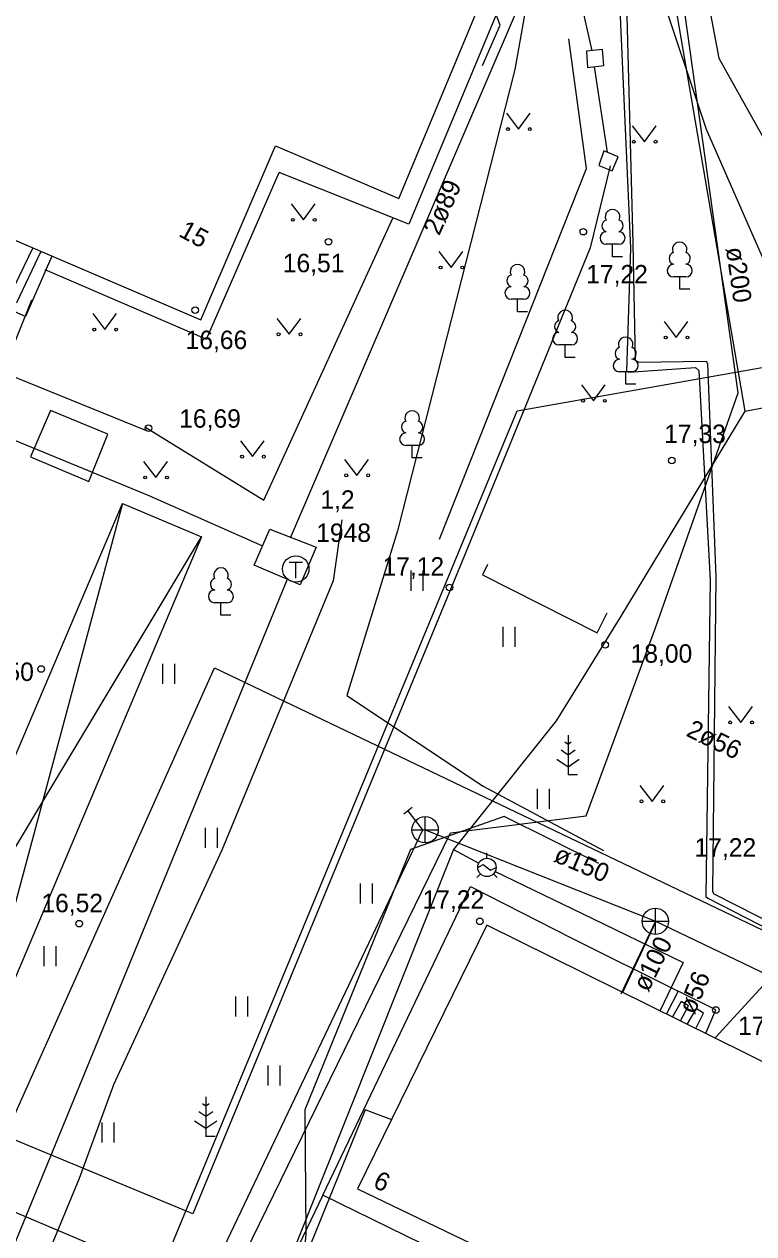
# Model space of a CAD drawing. Extents: x 713540 to 713867, y 6589774 to 6590061.
# Drawn here: x 713614.29 to 713641.99, y 6589963.85 to 6590009.83 of the extents above; entities that cross this region are included whole.
import ezdxf

# ---------------------------------------------------------------- set-up
doc = ezdxf.new("R2010")
doc.units = 0
for name, color, linetype in [('AED', 7, 'Continuous'), ('HALJASTUS', 7, 'Continuous'), ('HOONE', 7, 'Continuous'), ('HOONEDET', 7, 'Continuous'), ('KAEVU_NR', 7, 'Continuous'), ('KKAEV', 7, 'Continuous'), ('KORGUS', 7, 'Continuous'), ('KTRASS', 7, 'Continuous'), ('MPKAABEL', 7, 'Continuous'), ('PUU', 7, 'Continuous'), ('SITRASS', 7, 'Continuous'), ('TEE', 7, 'Continuous'), ('TKAEV', 7, 'Continuous'), ('TORU NR', 7, 'Continuous'), ('TTRASS', 7, 'Continuous'), ('VTRASS', 7, 'Continuous'), ('Слой 1', 7, 'Continuous')]:
    doc.layers.add(name, color=color, linetype=linetype)

msp = doc.modelspace()

# ---------------------------------------------------------------- linework, layer by layer
at = {"layer": 'AED'}
for points in [[(713618.488, 6590037.946), (713619.001, 6590034.99), (713622.312, 6590035.031), (713628.353, 6590032.257), (713630.993, 6590030.365), (713635.85, 6590008.82)], [(713635.64, 6590008.8), (713635.68, 6590008.18), (713636.3, 6590008.26), (713636.25, 6590008.86), (713635.64, 6590008.8)], [(713635.93, 6590008.21), (713636.42, 6590004.96)], [(713636.3, 6590005.01), (713636.11, 6590004.46), (713636.62, 6590004.25), (713636.85, 6590004.79), (713636.3, 6590005.01)], [(713636.535, 6590004.444), (713635.778, 6590001.331), (713631.008, 6589989.639), (713620.691, 6589964.611), (713584.43, 6589979.666), (713562.034, 6589989.021), (713563.098, 6589991.568)], [(713631.88, 6589989.288), (713631.697, 6589988.893), (713636.045, 6589986.694), (713636.43, 6589987.455)]]:
    msp.add_lwpolyline(points, dxfattribs=at)
at = {"layer": 'HALJASTUS'}
for p, q in [((713632.597, 6590006.447), (713633.06, 6590005.84)), ((713633.06, 6590005.84), (713633.506, 6590006.447)), ((713637.377, 6590005.967), (713637.84, 6590005.36)), ((713637.84, 6590005.36), (713638.286, 6590005.967)), ((713624.427, 6590002.997), (713624.89, 6590002.39)), ((713624.89, 6590002.39), (713625.336, 6590002.997)), ((713630.037, 6590001.187), (713630.5, 6590000.58)), ((713630.5, 6590000.58), (713630.946, 6590001.187)), ((713616.887, 6589998.827), (713617.35, 6589998.22)), ((713617.35, 6589998.22), (713617.796, 6589998.827)), ((713623.887, 6589998.647), (713624.35, 6589998.04)), ((713624.35, 6589998.04), (713624.796, 6589998.647)), ((713638.587, 6589998.527), (713639.05, 6589997.92)), ((713639.05, 6589997.92), (713639.496, 6589998.527)), ((713635.447, 6589996.117), (713635.91, 6589995.51)), ((713635.91, 6589995.51), (713636.356, 6589996.117)), ((713622.497, 6589993.997), (713622.96, 6589993.39)), ((713622.96, 6589993.39), (713623.406, 6589993.997)), ((713618.817, 6589993.207), (713619.28, 6589992.6)), ((713619.28, 6589992.6), (713619.726, 6589993.207)), ((713626.457, 6589993.287), (713626.92, 6589992.68)), ((713626.92, 6589992.68), (713627.366, 6589993.287)), ((713628.969, 6589989.058), (713628.969, 6589988.297)), ((713629.424, 6589989.058), (713629.424, 6589988.297)), ((713632.461, 6589986.926), (713632.461, 6589986.165)), ((713632.916, 6589986.926), (713632.916, 6589986.165)), ((713619.54, 6589985.522), (713619.54, 6589984.761)), ((713619.996, 6589985.522), (713619.996, 6589984.761)), ((713641.037, 6589983.897), (713641.5, 6589983.29)), ((713641.5, 6589983.29), (713641.946, 6589983.897)), ((713637.667, 6589980.897), (713638.13, 6589980.29)), ((713638.13, 6589980.29), (713638.576, 6589980.897)), ((713633.772, 6589980.771), (713633.772, 6589980.009)), ((713634.228, 6589980.771), (713634.228, 6589980.009)), ((713621.158, 6589979.286), (713621.158, 6589978.525)), ((713621.613, 6589979.286), (713621.613, 6589978.525)), ((713627.048, 6589977.166), (713627.048, 6589976.405)), ((713627.503, 6589977.166), (713627.503, 6589976.405)), ((713615.034, 6589974.782), (713615.034, 6589974.021)), ((713615.489, 6589974.782), (713615.489, 6589974.021)), ((713622.314, 6589972.876), (713622.314, 6589972.115)), ((713622.769, 6589972.876), (713622.769, 6589972.115)), ((713623.539, 6589970.251), (713623.539, 6589969.49)), ((713623.994, 6589970.251), (713623.994, 6589969.49)), ((713617.23, 6589968.083), (713617.23, 6589967.322)), ((713617.685, 6589968.083), (713617.685, 6589967.322))]:
    msp.add_line(p, q, dxfattribs=at)
for points in [[(713630.058, 6589990.26), (713635.64, 6590004.34), (713634.972, 6590009.265)], [(713618.87, 6589994.52), (713623.39, 6589991.74), (713628.29, 6590002.46)], [(713618.911, 6589994.383), (713603.441, 6590000.663)]]:
    msp.add_lwpolyline(points, dxfattribs=at)
for centre in [(713632.659, 6590005.84), (713633.488, 6590005.84), (713637.439, 6590005.36), (713638.268, 6590005.36), (713624.489, 6590002.39), (713625.318, 6590002.39), (713630.099, 6590000.58), (713630.928, 6590000.58), (713616.949, 6589998.22), (713617.778, 6589998.22), (713623.949, 6589998.04), (713624.778, 6589998.04), (713638.649, 6589997.92), (713639.478, 6589997.92), (713635.509, 6589995.51), (713636.338, 6589995.51), (713622.559, 6589993.39), (713623.388, 6589993.39), (713626.519, 6589992.68), (713627.348, 6589992.68), (713618.879, 6589992.6), (713619.708, 6589992.6), (713641.099, 6589983.29), (713641.928, 6589983.29), (713637.729, 6589980.29), (713638.558, 6589980.29)]:
    msp.add_circle(centre, 0.055, dxfattribs=at)
at = {"layer": 'HOONE'}
for p, q in [((713631.86, 6589978.13), (713631.86, 6589978.327)), ((713631.51, 6589977.778), (713631.721, 6589977.884)), ((713631.721, 6589977.884), (713631.999, 6589977.676)), ((713631.999, 6589977.676), (713632.21, 6589977.782)), ((713631.613, 6589977.533), (713631.473, 6589977.393)), ((713632.107, 6589977.533), (713632.247, 6589977.393))]:
    msp.add_line(p, q, dxfattribs=at)
for points in [[(713630.482, 6590060.636), (713633.183, 6590044.481), (713637.86, 6590017.28), (713638.858, 6590011.457), (713641.66, 6589995.12)], [(713611.945, 6590002.466), (713620.997, 6589998.591), (713623.828, 6590005.205), (713628.509, 6590003.201), (713631.396, 6590010.137), (713626.176, 6590012.308), (713625.646, 6590010.977), (713612.515, 6590016.682)], [(713641.66, 6589995.12), (713651.08, 6589996.88), (713659.244, 6589998.419), (713687.328, 6590003.385)], [(713641.66, 6589995.12), (713636.91, 6589987.262), (713634.49, 6589983.35), (713630.59, 6589978.46), (713620.519, 6589953.184), (713616.638, 6589944.685)], [(713665.097, 6589994.469), (713654.36, 6589992.62), (713659, 6589966.87), (713655.32, 6589963.97), (713631.86, 6589975.579), (713626.949, 6589965.568), (713655.111, 6589952.011), (713657.717, 6589953.998), (713658.827, 6589952.543), (713664.692, 6589957.048), (713664.664, 6589957.055), (713669.225, 6589960.582), (713668.167, 6589961.969), (713670.71, 6589963.909), (713665.097, 6589994.469)], [(713621.015, 6589990.338), (713611.877, 6589968.717), (713608.872, 6589970.068), (713618.021, 6589991.61), (713621.015, 6589990.338)], [(713630.59, 6589978.46), (713631.548, 6589977.939)], [(713632.171, 6589977.62), (713635.446, 6589976.042), (713639.31, 6589974.17), (713638.44, 6589972.34)]]:
    msp.add_lwpolyline(points, dxfattribs=at)
msp.add_circle((713631.86, 6589977.78), 0.35, dxfattribs=at)
at = {"layer": 'HOONEDET'}
for p, q in [((713618.021, 6589991.61), (713611.877, 6589968.717)), ((713608.872, 6589970.068), (713621.015, 6589990.338))]:
    msp.add_line(p, q, dxfattribs=at)
for points in [[(713625.431, 6590012.462), (713625.762, 6590013.293), (713632.366, 6590010.546), (713628.89, 6590002.231), (713623.97, 6590004.19)], [(713621.21, 6589997.86), (713623.97, 6590004.19)], [(713615.337, 6590001.014), (713614.341, 6589998.723), (713611.671, 6589999.883), (713612.664, 6590002.158)], [(713614.921, 6590001.192), (713613.991, 6589999.233), (713612.321, 6590000.023), (713613.163, 6590001.945)], [(713614.614, 6590001.323), (713613.921, 6589999.883), (713612.921, 6590000.283), (713613.559, 6590001.775)], [(713615.07, 6590000.5), (713621.21, 6589997.86)], [(713654.365, 6589993.337), (713665.759, 6589995.354), (713671.737, 6589963.499), (713669.522, 6589961.81), (713670.612, 6589960.382), (713665.868, 6589956.768), (713665.7, 6589956.808), (713658.611, 6589951.238), (713657.507, 6589952.685), (713655.117, 6589950.862), (713625.629, 6589965.327), (713631.231, 6589977.05), (713635.106, 6589975.077), (713639.12, 6589973.07)], [(713640.17, 6589971.48), (713640.55, 6589972.36), (713639.12, 6589973.07), (713638.68, 6589972.22)], [(713639.21, 6589971.95), (713639.51, 6589972.52), (713639.24, 6589972.68), (713638.91, 6589972.1)], [(713639.79, 6589971.66), (713640.09, 6589972.24), (713639.81, 6589972.42), (713639.47, 6589971.83)]]:
    msp.add_lwpolyline(points, dxfattribs=at)
at = {"layer": 'KKAEV'}
for p, q in [((713629.514, 6589978.71), (713629.514, 6589979.71)), ((713629.014, 6589979.21), (713630.014, 6589979.21)), ((713638.256, 6589975.233), (713638.256, 6589976.233)), ((713637.756, 6589975.733), (713638.756, 6589975.733))]:
    msp.add_line(p, q, dxfattribs=at)
for centre in [(713629.514, 6589979.21), (713638.256, 6589975.733)]:
    msp.add_circle(centre, 0.5, dxfattribs=at)
at = {"layer": 'KORGUS'}
for centre in [(713635.52, 6590001.94), (713625.84, 6590001.56), (713620.78, 6589998.96), (713619.01, 6589994.47), (713638.88, 6589993.24), (713630.44, 6589988.42), (713636.35, 6589986.24), (713614.93, 6589985.32), (713616.37, 6589975.64), (713631.59, 6589975.73), (713640.55, 6589972.36)]:
    msp.add_circle(centre, 0.125, dxfattribs=at)
at = {"layer": 'KTRASS'}
for p, q in [((713628.709, 6589979.819), (713629.018, 6589980.071)), ((713629.42, 6589979.213), (713628.859, 6589979.941)), ((713620.824, 6589961.132), (713629.42, 6589979.213))]:
    msp.add_line(p, q, dxfattribs=at)
for points in [[(713629.514, 6589979.21), (713638.256, 6589975.733)], [(713638.256, 6589975.733), (713636.946, 6589972.966)], [(713637.02, 6589973.04), (713638.29, 6589975.73)], [(713638.256, 6589975.733), (713644.655, 6589972.669)]]:
    msp.add_lwpolyline(points, dxfattribs=at)
at = {"layer": 'MPKAABEL'}
for points in [[(713634.872, 6590060.636), (713637.296, 6590044.981), (713639.214, 6590034.99), (713641.55, 6590020.81), (713640.247, 6590018.756), (713639.99, 6590012.096), (713640.67, 6590008.54), (713653.54, 6589985.5)], [(713631.696, 6590008.26), (713632.361, 6590009.786), (713631.878, 6590011.07), (713626.458, 6590013.001), (713624.501, 6590013.754), (713622.661, 6590013.508), (713613.306, 6590017.006)], [(713613.314, 6590017.025), (713622.509, 6590013.848), (713624.668, 6590014.258), (713633.443, 6590011.043), (713632.914, 6590008.103), (713628.469, 6589990.573), (713626.542, 6589984.315), (713631.711, 6589980.868), (713636.285, 6589978.421)], [(713626.354, 6589990.991), (713626.025, 6589988.675), (713621.796, 6589978.429), (713617.679, 6589969.517), (713616.38, 6589965.95), (713614.069, 6589960.385), (713612.538, 6589956.831), (713611.255, 6589953.855), (713609.284, 6589948.917), (713608.569, 6589945.656), (713614.381, 6589942.657), (713608.627, 6589929.201), (713606.65, 6589925.56), (713594.15, 6589930.93)], [(713640.53, 6589971.3), (713653.54, 6589985.5)], [(713636.109, 6589977.923), (713632.516, 6589979.71), (713628.954, 6589978.46), (713624.941, 6589968.562), (713624.988, 6589963.846), (713624.228, 6589955.304), (713624.309, 6589951.452), (713624.444, 6589944.99), (713624.264, 6589942.119), (713627.907, 6589940.465), (713624.829, 6589930.433), (713621.405, 6589921.156), (713617.009, 6589909.766)]]:
    msp.add_lwpolyline(points, dxfattribs=at)
at = {"layer": 'PUU'}
for p, q in [((713636.87, 6590001.465), (713636.39, 6590001.465)), ((713636.63, 6590000.99), (713636.63, 6590001.465)), ((713637.01, 6590000.99), (713636.63, 6590000.99)), ((713639.42, 6590000.225), (713638.94, 6590000.225)), ((713639.18, 6589999.75), (713639.18, 6590000.225)), ((713639.56, 6589999.75), (713639.18, 6589999.75)), ((713633.26, 6589999.375), (713632.78, 6589999.375)), ((713633.02, 6589998.9), (713633.02, 6589999.375)), ((713633.4, 6589998.9), (713633.02, 6589998.9)), ((713635.07, 6589997.635), (713634.59, 6589997.635)), ((713634.83, 6589997.16), (713634.83, 6589997.635)), ((713635.21, 6589997.16), (713634.83, 6589997.16)), ((713637.37, 6589996.615), (713636.89, 6589996.615)), ((713637.13, 6589996.14), (713637.13, 6589996.615)), ((713637.51, 6589996.14), (713637.13, 6589996.14)), ((713629.26, 6589993.815), (713628.78, 6589993.815)), ((713629.02, 6589993.34), (713629.02, 6589993.815)), ((713629.4, 6589993.34), (713629.02, 6589993.34)), ((713621.999, 6589987.841), (713621.519, 6589987.841)), ((713621.759, 6589987.366), (713621.759, 6589987.841)), ((713622.139, 6589987.366), (713621.759, 6589987.366)), ((713634.941, 6589982.801), (713634.941, 6589981.301)), ((713634.941, 6589982.051), (713634.674, 6589982.229)), ((713634.941, 6589982.451), (713634.817, 6589982.534)), ((713635.065, 6589982.534), (713634.941, 6589982.451)), ((713635.208, 6589982.229), (713634.941, 6589982.051)), ((713634.517, 6589981.891), (713634.941, 6589981.608)), ((713634.941, 6589981.608), (713635.365, 6589981.891)), ((713635.301, 6589981.301), (713634.941, 6589981.301)), ((713621.181, 6589969.056), (713621.181, 6589967.556)), ((713621.181, 6589968.306), (713620.915, 6589968.484)), ((713621.181, 6589968.706), (713621.057, 6589968.789)), ((713621.306, 6589968.789), (713621.181, 6589968.706)), ((713621.448, 6589968.484), (713621.181, 6589968.306)), ((713620.757, 6589968.145), (713621.181, 6589967.863)), ((713621.181, 6589967.863), (713621.605, 6589968.145)), ((713621.541, 6589967.556), (713621.181, 6589967.556))]:
    msp.add_line(p, q, dxfattribs=at)
for centre, radius, start, end in [((713636.46, 6590002.163), 0.233, 109.0217, 253.1415), ((713636.63, 6590002.51), 0.277, 332.5799, 207.4201), ((713636.8, 6590002.163), 0.233, 286.8508, 70.9859), ((713636.393, 6590001.702), 0.238, 90.0016, 269.3953), ((713636.867, 6590001.702), 0.238, 270.6047, 89.9984), ((713639.18, 6590001.27), 0.277, 332.5799, 207.4201), ((713639.01, 6590000.923), 0.233, 109.0217, 253.1415), ((713639.35, 6590000.923), 0.233, 286.8508, 70.9859), ((713633.02, 6590000.42), 0.277, 332.5799, 207.4201), ((713638.943, 6590000.462), 0.238, 90.0016, 269.3953), ((713639.417, 6590000.462), 0.238, 270.6047, 89.9984), ((713632.85, 6590000.073), 0.233, 109.0217, 253.1415), ((713633.19, 6590000.073), 0.233, 286.8508, 70.9859), ((713632.783, 6589999.612), 0.238, 90.0016, 269.3953), ((713633.257, 6589999.612), 0.238, 270.6047, 89.9984), ((713634.83, 6589998.68), 0.277, 332.5799, 207.4201), ((713634.66, 6589998.333), 0.233, 109.0217, 253.1415), ((713635, 6589998.333), 0.233, 286.8508, 70.9859), ((713634.593, 6589997.872), 0.238, 90.0016, 269.3953), ((713635.067, 6589997.872), 0.238, 270.6047, 89.9984), ((713637.13, 6589997.66), 0.277, 332.5799, 207.4201), ((713636.96, 6589997.313), 0.233, 109.0217, 253.1415), ((713637.3, 6589997.313), 0.233, 286.8508, 70.9859), ((713636.893, 6589996.852), 0.238, 90.0016, 269.3953), ((713637.367, 6589996.852), 0.238, 270.6047, 89.9984), ((713629.02, 6589994.86), 0.277, 332.5799, 207.4201), ((713628.85, 6589994.513), 0.233, 109.0217, 253.1415), ((713629.19, 6589994.513), 0.233, 286.8508, 70.9859), ((713628.783, 6589994.052), 0.238, 90.0016, 269.3953), ((713629.257, 6589994.052), 0.238, 270.6047, 89.9984), ((713621.759, 6589988.886), 0.277, 332.5799, 207.4201), ((713621.589, 6589988.539), 0.233, 109.0217, 253.1415), ((713621.929, 6589988.539), 0.233, 286.8508, 70.9859), ((713621.521, 6589988.079), 0.238, 90.0016, 269.3953), ((713621.996, 6589988.079), 0.238, 270.6047, 89.9984)]:
    msp.add_arc(centre, radius, start, end, dxfattribs=at)
at = {"layer": 'SITRASS'}
for points in [[(713634.735, 6590060.636), (713639.6, 6590031.34), (713639.42, 6590021.66), (713636.56, 6590016.77), (713638.404, 6590011.201), (713640.18, 6590005.84), (713646.71, 6589990.97), (713657.77, 6589965.9)], [(713628.246, 6589968.19), (713627.234, 6589968.567), (713624.83, 6589962.636), (713623.526, 6589951.809), (713623.516, 6589951.814), (713622.543, 6589943.796)]]:
    msp.add_lwpolyline(points, dxfattribs=at)
at = {"layer": 'TEE'}
for points in [[(713614.57, 6589999.34), (713613.707, 6589997.19), (713603.922, 6590001.326), (713591.825, 6589974.045), (713621.261, 6589961.576), (713622.688, 6589963.147), (713630.481, 6589979.098), (713635.632, 6589979.743), (713638.264, 6589986.883), (713641.401, 6589995.818), (713639.191, 6590011.645), (713635.853, 6590032.559), (713631.194, 6590060.636)], [(713615.29, 6589995.15), (713614.52, 6589993.38)], [(713617.46, 6589994.25), (713615.29, 6589995.15)], [(713616.74, 6589992.45), (713617.46, 6589994.25)], [(713614.52, 6589993.38), (713616.74, 6589992.45)], [(713625.629, 6589965.327), (713624.266, 6589962.475), (713623.751, 6589960.756), (713641.009, 6589953.207), (713653.169, 6589948.075), (713657.982, 6589947.86), (713664.159, 6589951.614), (713669.174, 6589954.004), (713672.84, 6589955.104)]]:
    msp.add_lwpolyline(points, dxfattribs=at)
at = {"layer": 'TKAEV'}
for p, q in [((713624.351, 6589989.374), (713624.851, 6589989.374)), ((713624.601, 6589988.774), (713624.601, 6589989.374))]:
    msp.add_line(p, q, dxfattribs=at)
msp.add_circle((713624.601, 6589989.124), 0.5, dxfattribs=at)
at = {"layer": 'TTRASS'}
for points in [[(713628.896, 6590060.636), (713628.908, 6590060.564), (713631.035, 6590048.786), (713632.894, 6590037.061), (713635.242, 6590025.21), (713636.781, 6590013.249), (713637.307, 6590001.316), (713637.157, 6589996.645), (713637.245, 6589996.6), (713639.784, 6589996.778), (713639.911, 6589996.659), (713640.338, 6589988.697), (713640.169, 6589976.679), (713640.253, 6589976.609), (713650.804, 6589971.182), (713650.915, 6589970.999), (713652.857, 6589965.719), (713652.647, 6589965.295)], [(713629.199, 6590060.636), (713631.21, 6590049.147), (713633.256, 6590037.367), (713635.386, 6590025.437), (713637.081, 6590013.496), (713637.406, 6590001.507), (713637.495, 6589997.061), (713637.616, 6589996.981), (713640.19, 6589997.018), (713640.241, 6589996.932), (713640.549, 6589988.818), (713640.423, 6589976.86), (713640.479, 6589976.779), (713651.149, 6589971.354), (713651.264, 6589971.081), (713653.226, 6589965.534), (713653.017, 6589965.111)], [(713633.747, 6590012.114), (713624.389, 6589990.298)], [(713609.26, 6589995.35), (713610.09, 6589995.59), (713619.026, 6589991.91), (713623.336, 6589990.002)], [(713623.615, 6589990.64), (713625.375, 6589989.95), (713624.765, 6589988.52), (713623.015, 6589989.27), (713623.615, 6589990.64)], [(713624.26, 6589988.69), (713611.403, 6589957.349), (713609.73, 6589953.27), (713632.9, 6589943.77)]]:
    msp.add_lwpolyline(points, dxfattribs=at)
at = {"layer": 'VTRASS'}
msp.add_lwpolyline([(713608.676, 6589956.662), (713621.51, 6589985.36), (713642.92, 6589975.12), (713654.41, 6589964.42)], dxfattribs=at)
at = {"layer": 'Слой 1'}
msp.add_lwpolyline([(713667.77, 6590001.29), (713675.57, 6589961), (713658.19, 6589946.81), (713619.46, 6589962.4), (713633.01, 6589995.13)], close=True, dxfattribs=at)

# ---------------------------------------------------------------- texts
at = {"layer": 'HOONE'}
for s, rotation, p in [('15', 331.372, (713620.116, 6590001.79)), ('6', 334.2405, (713627.493, 6589965.647))]:
    msp.add_text(s, height=0.7, rotation=rotation, dxfattribs=at).set_placement(p)
at = {"layer": 'KAEVU_NR'}
msp.add_text('1948', height=0.7, dxfattribs=at).set_placement((713625.375, 6589990.15))
at = {"layer": 'KORGUS'}
for s, p in [('16,51', (713624.107, 6590000.4)), ('17,22', (713635.628, 6589999.975)), ('16,66', (713620.415, 6589997.48)), ('16,69', (713620.172, 6589994.49)), ('17,33', (713638.591, 6589993.91)), ('17,12', (713627.893, 6589988.87)), ('18,00', (713637.315, 6589985.56)), ('16,50', (713612.311, 6589984.865)), ('17,22', (713639.743, 6589978.19)), ('16,52', (713614.938, 6589976.075)), ('17,22', (713629.413, 6589976.21)), ('17,30', (713641.395, 6589971.41))]:
    msp.add_text(s, height=0.7, dxfattribs=at).set_placement(p)
at = {"layer": 'TORU NR'}
for s, rotation, p in [('2ø89', 66.0375, (713630.046, 6590001.76)), ('ø200', 278.1301, (713640.932, 6590001.312)), ('2ø56', 334.1129, (713639.386, 6589982.795)), ('ø150', 337.0459, (713634.352, 6589978.021)), ('ø100', 63.9046, (713637.985, 6589973.009)), ('ø56', 67.4258, (713639.738, 6589972.156))]:
    msp.add_text(s, height=0.7, rotation=rotation, dxfattribs=at).set_placement(p)
msp.add_text('1,2', height=0.7, dxfattribs=at).set_placement((713625.534, 6589991.41))

doc.saveas('drawing.dxf')
